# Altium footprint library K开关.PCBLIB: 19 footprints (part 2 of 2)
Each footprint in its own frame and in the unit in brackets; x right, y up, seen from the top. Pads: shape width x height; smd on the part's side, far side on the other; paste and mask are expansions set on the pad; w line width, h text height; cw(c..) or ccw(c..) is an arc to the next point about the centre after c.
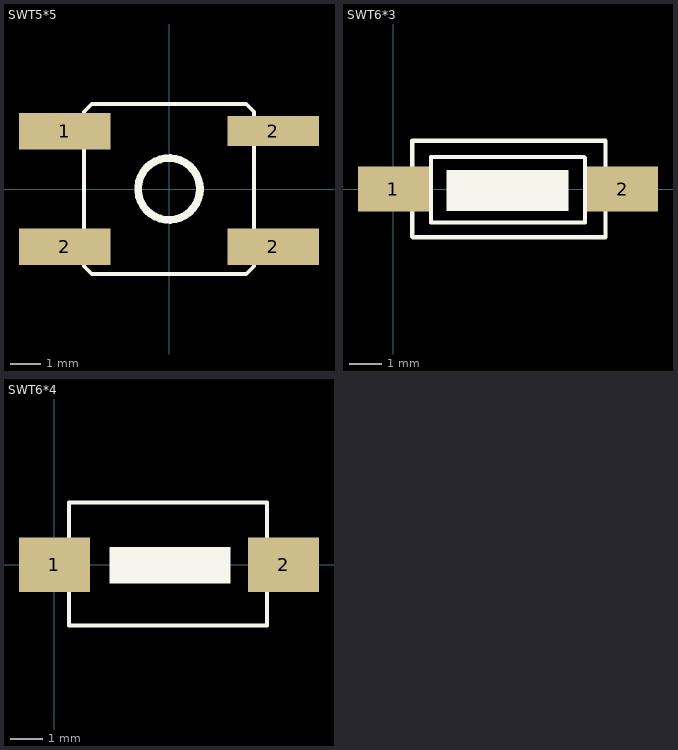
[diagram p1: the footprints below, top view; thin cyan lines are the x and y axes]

## SWT5*5 [mm]
pads (4):
  rect 3x1.2 smd: 1(-3.429,1.905) 2(-3.429,-1.905) 2(3.429,-1.905)
  rect 3x1 smd: 2(3.429,1.905)
TopOverlay:
  circle w0.254: c0,0 r1.016
  lines w0.127: -2.794,-2.54 -2.794,2.54 -2.54,2.794 0,2.794 2.54,2.794 2.794,2.54 2.794,-2.54 2.54,-2.794 -2.54,-2.794 -2.794,-2.54

## SWT6*3 [mm]
pads (2):
  rect 2.2x1.4 smd: 1(0,0) 2(7.112,0)
TopOverlay:
  rectangle: 1.651,-0.686 5.436,0.584
  lines w0.127: 0.584,-1.473 0.584,0 0.584,1.499 6.579,1.499 6.579,-1.499 0.61,-1.499 0.584,-1.473 ; 1.168,-1.041 1.168,0.991 5.918,0.991 5.944,0.965 5.944,-1.041 1.168,-1.041

## SWT6*4 [mm]
pads (2):
  rect 2.2x1.7 smd: 1(0,0) 2(7.112,0)
TopOverlay:
  rectangle: 1.702,-0.584 5.461,0.559
  lines w0.127: 0.457,-1.88 0.457,1.93 6.604,1.93 6.604,-1.88 0.457,-1.88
